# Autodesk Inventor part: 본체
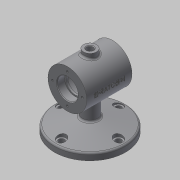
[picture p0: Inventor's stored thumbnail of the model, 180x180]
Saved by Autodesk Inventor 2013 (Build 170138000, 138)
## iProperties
Created: 2018-12
Part Number: 본체
Material: Generic
Document SubType Name: Modeling
Designer: Administrator
Density: 1 g/cm^3
Author: Administrator
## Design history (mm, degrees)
sketch "스케치2"
  geometry: L1 (-35, 0)-(35, 0); L2 (0, 0)-(0, 30); L3 (-35, 16)-(-23, 16); L4 (-23, 14)-(-20, 14); L5 (-20, 14)-(-20, 25); L6 (-20, 25)-(0, 25); L7 (-35, 16)-(-35, 30); L8 (-35, 30)-(0, 30); L9 (-23, 16)-(-23, 14); L10 (35, 16)-(23, 16); L11 (23, 14)-(20, 14); L12 (20, 14)-(20, 25); L13 (20, 25)-(0, 25); L14 (35, 16)-(35, 30); L15 (35, 30)-(0, 30); L16 (23, 16)-(23, 14); 1 further point
  constraints: 32 end point, 6 symmetric about line, 4 perpendicular, 2 coincident, 2 parallel, 1 horizontal, 1 midpoint, 1 point on line, 1 vertical alignment
  dimensions: "d0" = 70 distance of L1.start L1.end; "d3" = 32 diameter of L3 L1; "d4" = 28 diameter of L4 L1; "d5" = 12 distance of L3.start L3.end; "d6" = 3 distance of L4.start L4.end; "d7" = 50 diameter of L6 L1; "d8" = 20 distance of L5.end L6.end; "d9" = 60 diameter of L8 L1
revolve "회전1" sketch "스케치2" stored, may be unused: angle "d10" = 90 deg
node "작업 평면1"
sketch "스케치4"
  geometry: C1 r 55 at (0, 0); 1 further point
  constraints: 1 centre point, 1 coincident
  dimensions: "d12" = 110 diameter of C1
extrude "돌출1" join sketch "스케치4" distance "d14" = 11; taper "d15" = 0 deg
sketch "스케치6"
  geometry: C1 r 55 at (0, 0) reference; C2 r 12 at (0, 0)
  constraints: 1 centre point, 1 coincident
  dimensions: "d16" = 24 diameter of C2
extrude "돌출2" join sketch "스케치6" stored distance "d18" = 10; taper "d19" = 0 deg
node "작업 평면2"
sketch "스케치7"
  geometry: C1 r 10 at (0, 0); 1 further point
  constraints: 1 centre point, 1 coincident
  dimensions: "d21" = 20 diameter of C1
extrude "돌출3" join sketch "스케치7" stored distance "d23" = 10; taper "d24" = 0 deg
sketch "스케치8"
  geometry: C1 r 10 at (0, 0) reference; C2 r 5 at (0, 0)
  constraints: 1 centre point, 1 coincident
  dimensions: "d25" = 10 diameter of C2
extrude "돌출4" cut sketch "스케치8" stored distance "d27" = 10; taper "d28" = 0 deg
node "작업 평면3"
sketch "스케치10"
  geometry: 2 further points
  constraints: 1 coincident, 1 other
feature "엠보싱1" sketch "스케치10" dims "d0" = 70, "d3" = 32, "d4" = 28, "d5" = 12, "d6" = 3, "d7" = 50, "d8" = 20, "d9" = 60, "d29" = 0.5, "d30" = 0
chamfer "모따기1" distance "d31" = 1; stored, may be unused: second distance "d32" = 2, angle "d33" = 45 deg
sketch "스케치11"
  geometry: C1 r 30 at (0, 0) reference; 1 further point
  constraints: 1 vertical alignment
  dimensions: "d34" = 23 distance of C1.centre point (0, 23)
hole "구멍1" sketch "스케치11" at (0, 23) diameter "d35" = 3.242; stored, may be unused: countersink angle "d39" = 90 deg, drill point angle "d41" = 118 deg; dims "d36" = 8, "d37" = 4, "d38" = 2, "d40" = 10
fillet "모깎기1" dims "d45" = 3
sketch "스케치12"
  geometry: L1 (-64, -12)-(-27.495, -12) reference; L2 (-64, 52)-(-64, -52) reference; L3 (-75, -55)-(-67, -55) reference; L4 (-75, 55)-(-75, -55) reference; L5 (-53.176, -12)-(-64.102, -52.776); L6 (0, 0)-(-76.327, 0); A1 r 3 centre (-67, -52) between (-67, -55) and (-64, -52) reference
  constraints: 4 end point, 1 perpendicular, 1 point on circle, 1 point on line, 1 tangent
  dimensions: "d52" = 75 deg angle of L3 L5
revolve "회전2" sketch "스케치12" stored, may be unused: angle "d53" = 90 deg
fillet "모깎기2" dims "d54" = 3
sketch "스케치13"
  geometry: C1 r 55 at (0, 0) reference; C2 r 4.5 at (44, 0)
  constraints: 1 centre point, 1 horizontal alignment
  dimensions: "d55" = 9 diameter of C2; "d57" = 44 distance of C1.centre C2.centre
extrude "돌출5" cut sketch "스케치13" distance "d58" = 10; taper "d59" = 0 deg
sketch "스케치14"
  geometry: C1 r 4.5 at (0, 0) reference; C2 r 7 at (0, 0); 1 further point
  constraints: 1 centre point, 1 coincident
  dimensions: "d60" = 14 diameter of C2
extrude "돌출6" cut sketch "스케치14" stored distance "d62" = 10; taper "d63" = 0 deg
sketch "스케치15"
  geometry: C1 r 4.5 at (0, 0) reference; 4 further points
  constraints: 3 other
extrude "돌출7" cut sketch "스케치15" stored distance "d67" = 10; taper "d68" = 0 deg
chamfer "모따기2" distance "d69" = 1; stored, may be unused: second distance "d70" = 2, angle "d71" = 45 deg
fillet "모깎기3" dims "d72" = 3
fillet "모깎기4" dims "d73" = 0.3
node "솔리드1"
pattern_circular "원형 패턴1" dims angle "d43" = 360 deg
mirror "대칭1"
pattern_circular "원형 패턴2" dims angle "d65" = 360 deg
node "투영된 루프1"
other parameters: "d11" = -75, "d20" = -112
